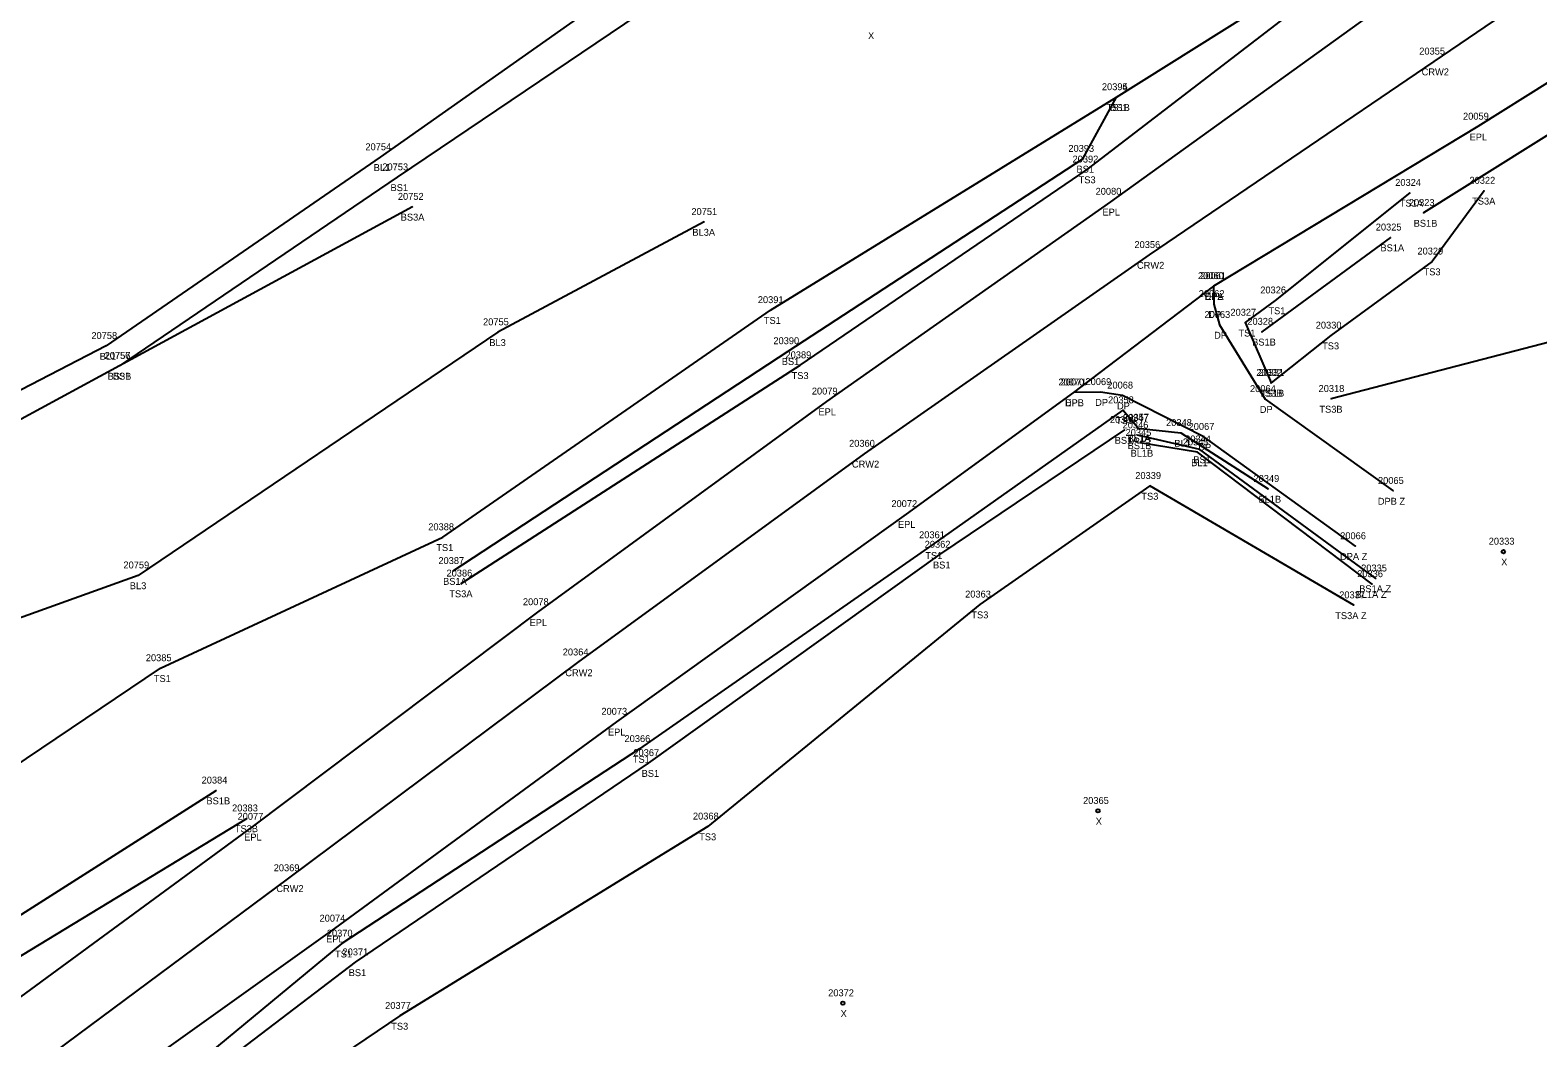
# Model space of a CAD drawing. Extents: x 1813127 to 1814107, y 1178171 to 1179078.
# Drawn here: x 1813586.1 to 1813803.8, y 1178473.8 to 1178619.3 of the extents above; entities that cross this region are included whole.
import ezdxf

# ---------------------------------------------------------------- set-up
doc = ezdxf.new("R2010")
doc.units = 0
for name, color, linetype in [('RD_DTM_BkLn1', 7, 'Continuous'), ('RD_DTM_BkLn2', 7, 'Continuous'), ('RD_EX_Driveway', 7, 'Continuous'), ('RD_EX_Driveway_txCode', 7, 'Continuous'), ('RD_EX_Road', 7, 'Continuous'), ('RD_EX_Road_txCode', 7, 'Continuous'), ('RD_SMD_Locator', 7, 'Continuous'), ('RD_SMD_Misc', 7, 'Continuous')]:
    doc.layers.add(name, color=color, linetype=linetype)

msp = doc.modelspace()

# ---------------------------------------------------------------- linework, layer by layer
at = {"layer": 'RD_DTM_BkLn1'}
for points in [[(1813684.91, 1178649.24), (1813672.9, 1178626.57), (1813636.59, 1178600.97), (1813597.02, 1178573.71), (1813553.38, 1178551.14), (1813526.62, 1178527.89)], [(1813831.28, 1178643.33), (1813821.11, 1178637.41), (1813809.78, 1178629.12), (1813788.78, 1178614.79), (1813747.67, 1178586.85), (1813706.5, 1178558.14), (1813665.11, 1178528), (1813623.37, 1178496.83), (1813582.75, 1178466.66)], [(1813683.38, 1178591.62), (1813653.58, 1178575.69), (1813601.65, 1178540.57), (1813550.07, 1178522.01), (1813545.91, 1178506.15)], [(1813745.95, 1178561.82), (1813752.22, 1178561.14), (1813764.83, 1178553.06)], [(1813779.84, 1178539.31), (1813754.64, 1178558.34), (1813746.36, 1178559.71)]]:
    msp.add_lwpolyline(points, dxfattribs=at)
at = {"layer": 'RD_DTM_BkLn2'}
for p, q in [((1813641.28, 1178593.81), (1813598.95, 1178570.83)), ((1813782.5, 1178589.38), (1813763.95, 1178575.76)), ((1813570.91, 1178482.75), (1813612.94, 1178509.5)), ((1813573.76, 1178478.94), (1813617.33, 1178505.47))]:
    msp.add_line(p, q, dxfattribs=at)
for points in [[(1813648.32, 1178539.4), (1813697.26, 1178570.92), (1813738.71, 1178599.2), (1813778.43, 1178629.72), (1813788.89, 1178635.21), (1813789.75, 1178645.61), (1813795.55, 1178639.4), (1813796.73, 1178649.77), (1813786.93, 1178659.75), (1813776.01, 1178666.91), (1813768.6, 1178671.47), (1813763.23, 1178675.13), (1813760.53, 1178679.87)], [(1813647.13, 1178541.2), (1813695.54, 1178572.96), (1813738.1, 1178600.74), (1813742.95, 1178609.65), (1813776.97, 1178631.04), (1813783.78, 1178636.69), (1813785.55, 1178637.95), (1813783.65, 1178657.07), (1813774.21, 1178663.42), (1813755.25, 1178670.65), (1813744.09, 1178675.31)], [(1813687.73, 1178647.6), (1813673.94, 1178621.63), (1813639.04, 1178598.07), (1813598.95, 1178570.83), (1813556.33, 1178547.73), (1813528.18, 1178524.13)], [(1814014.78, 1178443.42), (1813981.68, 1178475.25), (1813945.25, 1178510.83), (1813909.11, 1178545.75), (1813871.28, 1178580.16), (1813838.14, 1178611.58), (1813831.82, 1178617.25), (1813823.34, 1178615.53), (1813787.27, 1178592.92)], [(1813561.84, 1178498.2), (1813604.88, 1178527.17), (1813645.67, 1178546.08), (1813692.97, 1178578.89), (1813742.95, 1178609.65)], [(1813893.16, 1178338.84), (1813921.32, 1178364.43), (1813929.94, 1178352.15), (1813936.66, 1178353.94), (1813964.13, 1178381.53), (1813993.38, 1178417.59), (1814007.74, 1178441.51), (1813972.38, 1178457.8), (1813931.97, 1178507.78), (1813904.27, 1178536.29), (1813860.78, 1178571.07), (1813835.97, 1178602.37), (1813828.98, 1178599.83), (1813813.84, 1178586.1), (1813811.52, 1178575.86), (1813773.95, 1178566.06)], [(1813785.3, 1178595.83), (1813765.84, 1178580.29), (1813761.51, 1178577.07), (1813765.25, 1178568.38)], [(1813796.03, 1178596.13), (1813788.52, 1178585.91), (1813773.87, 1178575.21), (1813765.25, 1178568.38)], [(1813746.03, 1178561.9), (1813743.83, 1178564.42), (1813716.29, 1178544.93), (1813674.06, 1178515.49), (1813631.05, 1178487.38), (1813591.54, 1178454.7)], [(1813744.11, 1178561.57), (1813717.38, 1178543.56), (1813675.31, 1178513.46), (1813633, 1178484.68), (1813592.1, 1178453.49)], [(1813780.39, 1178540.13), (1813754.97, 1178558.77), (1813745.96, 1178560.8)], [(1813777.22, 1178536.25), (1813747.77, 1178553.49), (1813723.22, 1178536.36), (1813683.91, 1178504.3), (1813639.44, 1178476.94), (1813596.75, 1178448.06)]]:
    msp.add_lwpolyline(points, dxfattribs=at)
at = {"layer": 'RD_EX_Driveway'}
for points in [[(1813756.93, 1178582.36), (1813756.99, 1178579.76), (1813757.82, 1178576.75), (1813764.4, 1178566.04), (1813782.88, 1178552.77)], [(1813777.44, 1178544.79), (1813755.53, 1178560.58), (1813743.79, 1178566.55), (1813740.64, 1178567.05), (1813736.74, 1178567)]]:
    msp.add_lwpolyline(points, dxfattribs=at)
at = {"layer": 'RD_EX_Road'}
for points in [[(1813577.25, 1178474.27), (1813618.17, 1178504.26), (1813659.38, 1178535.26), (1813701.1, 1178565.69), (1813742.11, 1178594.54), (1813782.72, 1178623.8), (1813791.22, 1178630.12), (1813798.98, 1178638.62), (1813801.09, 1178645.46), (1813800.26, 1178651.57), (1813775.58, 1178673.13), (1813768.46, 1178675.91), (1813762.33, 1178681.89)], [(1813815.99, 1178618.51), (1813795.14, 1178605.39), (1813756.93, 1178582.36), (1813736.74, 1178567), (1813712.58, 1178549.43), (1813670.71, 1178519.43), (1813630, 1178489.55), (1813588.23, 1178459.7)]]:
    msp.add_lwpolyline(points, dxfattribs=at)
at = {"layer": 'RD_SMD_Locator'}
for centre, radius in [((1813788.78, 1178614.79), 0.001), ((1813742.95, 1178609.65), 0.001), ((1813742.95, 1178609.65), 0.001), ((1813795.14, 1178605.39), 0.001), ((1813636.59, 1178600.97), 0.001), ((1813738.1, 1178600.74), 0.001), ((1813639.04, 1178598.07), 0.001), ((1813738.71, 1178599.2), 0.001), ((1813785.3, 1178595.83), 0.001), ((1813796.03, 1178596.13), 0.001), ((1813641.28, 1178593.81), 0.001), ((1813742.11, 1178594.54), 0.001), ((1813683.38, 1178591.62), 0.001), ((1813787.27, 1178592.92), 0.001), ((1813782.5, 1178589.38), 0.001), ((1813747.67, 1178586.85), 0.001), ((1813788.52, 1178585.91), 0.001), ((1813756.93, 1178582.36), 0.001), ((1813756.93, 1178582.36), 0.001), ((1813765.84, 1178580.29), 0.001), ((1813692.97, 1178578.89), 0.001), ((1813756.99, 1178579.76), 0.001), ((1813653.58, 1178575.69), 0.001), ((1813757.82, 1178576.75), 0.001), ((1813761.51, 1178577.07), 0.001), ((1813763.95, 1178575.76), 0.001), ((1813597.02, 1178573.71), 0.001), ((1813773.87, 1178575.21), 0.001), ((1813695.54, 1178572.96), 0.001), ((1813598.95, 1178570.83), 0.001), ((1813598.95, 1178570.83), 0.001), ((1813697.26, 1178570.92), 0.001), ((1813736.74, 1178567), 0.001), ((1813736.74, 1178567), 0.001), ((1813740.64, 1178567.05), 0.001), ((1813765.25, 1178568.38), 0.001), ((1813765.25, 1178568.38), 0.001), ((1813701.1, 1178565.69), 0.001), ((1813743.79, 1178566.55), 0.001), ((1813764.4, 1178566.04), 0.001), ((1813773.95, 1178566.06), 0.001), ((1813743.83, 1178564.42), 0.001), ((1813744.11, 1178561.57), 0.001), ((1813745.95, 1178561.82), 0.001), ((1813745.96, 1178560.8), 0.001), ((1813746.03, 1178561.9), 0.001), ((1813752.22, 1178561.14), 0.001), ((1813755.53, 1178560.58), 0.001), ((1813706.5, 1178558.14), 0.001), ((1813746.36, 1178559.71), 0.001), ((1813754.64, 1178558.34), 0.001), ((1813754.97, 1178558.77), 0.001), ((1813747.77, 1178553.49), 0.001), ((1813764.83, 1178553.06), 0.001), ((1813782.88, 1178552.77), 0.001), ((1813712.58, 1178549.43), 0.001), ((1813645.67, 1178546.08), 0.001), ((1813716.29, 1178544.93), 0.001), ((1813717.38, 1178543.56), 0.001), ((1813777.44, 1178544.79), 0.001), ((1813798.81, 1178544), 0.25), ((1813647.13, 1178541.2), 0.001), ((1813601.65, 1178540.57), 0.001), ((1813648.32, 1178539.4), 0.001), ((1813779.84, 1178539.31), 0.001), ((1813780.39, 1178540.13), 0.001), ((1813723.22, 1178536.36), 0.001), ((1813659.38, 1178535.26), 0.001), ((1813777.22, 1178536.25), 0.001), ((1813665.11, 1178528), 0.001), ((1813604.88, 1178527.17), 0.001), ((1813670.71, 1178519.43), 0.001), ((1813674.06, 1178515.49), 0.001), ((1813675.31, 1178513.46), 0.001), ((1813612.94, 1178509.5), 0.001), ((1813740.26, 1178506.55), 0.25), ((1813617.33, 1178505.47), 0.001), ((1813618.17, 1178504.26), 0.001), ((1813683.91, 1178504.3), 0.001), ((1813623.37, 1178496.83), 0.001), ((1813630, 1178489.55), 0.001), ((1813631.05, 1178487.38), 0.001), ((1813633, 1178484.68), 0.001), ((1813703.41, 1178478.77), 0.25), ((1813639.44, 1178476.94), 0.001)]:
    msp.add_circle(centre, radius, dxfattribs=at)

# ---------------------------------------------------------------- texts
at = {"layer": 'RD_EX_Driveway_txCode'}
for s, p in [('20061', (1813755.03, 1178583.36)), ('20062', (1813754.81, 1178580.76)), ('DPA', (1813755.66, 1178580.36)), ('20063', (1813755.64, 1178577.75)), ('DP', (1813756.21, 1178577.76)), ('DP', (1813757.04, 1178574.75)), ('20070', (1813734.55, 1178568)), ('20069', (1813738.46, 1178568.05)), ('20068', (1813741.61, 1178567.55)), ('20064', (1813762.22, 1178567.04)), ('DPB', (1813735.49, 1178565)), ('DP', (1813739.86, 1178565.05)), ('DP', (1813743.01, 1178564.55)), ('DP', (1813763.63, 1178564.04)), ('20067', (1813753.35, 1178561.58)), ('DP', (1813754.75, 1178558.58)), ('20065', (1813780.7, 1178553.77)), ('DPB Z', (1813780.68, 1178550.77)), ('20066', (1813775.24, 1178545.79)), ('DPA Z', (1813775.22, 1178542.79))]:
    msp.add_text(s, height=1, dxfattribs=at).set_placement(p)
at = {"layer": 'RD_EX_Road_txCode'}
for s, p in [('20059', (1813792.98, 1178606.39)), ('EPL', (1813793.93, 1178603.39)), ('20080', (1813739.92, 1178595.54)), ('EPL', (1813740.91, 1178592.54)), ('20060', (1813754.71, 1178583.36)), ('EPL', (1813755.73, 1178580.36)), ('20071', (1813734.87, 1178568)), ('20079', (1813698.94, 1178566.69)), ('EPL', (1813699.9, 1178563.69)), ('EPL', (1813735.54, 1178565)), ('20072', (1813710.43, 1178550.43)), ('EPL', (1813711.38, 1178547.43)), ('20078', (1813657.22, 1178536.26)), ('EPL', (1813658.18, 1178533.26)), ('20073', (1813668.55, 1178520.43)), ('EPL', (1813669.5, 1178517.43)), ('20077', (1813616.01, 1178505.26)), ('EPL', (1813616.96, 1178502.26)), ('20074', (1813627.85, 1178490.55)), ('EPL', (1813628.8, 1178487.55))]:
    msp.add_text(s, height=1, dxfattribs=at).set_placement(p)
at = {"layer": 'RD_SMD_Misc'}
for s, p in [('X', (1813707.06, 1178618.02)), ('20355', (1813786.66, 1178615.79)), ('CRW2', (1813787.01, 1178612.79)), ('20394', (1813740.83, 1178610.65)), ('20395', (1813740.83, 1178610.65)), ('TS1B', (1813741.52, 1178607.65)), ('BS1', (1813742.01, 1178607.65)), ('20754', (1813634.47, 1178601.97)), ('20393', (1813735.99, 1178601.74)), ('BL1', (1813635.67, 1178598.97)), ('20753', (1813636.92, 1178599.07)), ('20392', (1813736.59, 1178600.2)), ('BS1', (1813737.16, 1178598.74)), ('TS3', (1813737.47, 1178597.2)), ('20324', (1813783.19, 1178596.83)), ('20322', (1813793.91, 1178597.13)), ('BS1', (1813638.1, 1178596.07)), ('20752', (1813639.16, 1178594.81)), ('TS3A', (1813794.3, 1178594.13)), ('20751', (1813681.55, 1178592.62)), ('TS1A', (1813783.85, 1178593.83)), ('20323', (1813785.15, 1178593.92)), ('BS3A', (1813639.57, 1178591.81)), ('20325', (1813780.38, 1178590.38)), ('BS1B', (1813785.85, 1178590.92)), ('BL3A', (1813681.69, 1178589.62)), ('20356', (1813745.53, 1178587.85)), ('BS1A', (1813781.06, 1178587.38)), ('20329', (1813786.4, 1178586.91)), ('CRW2', (1813745.9, 1178584.85)), ('TS3', (1813787.28, 1178583.91)), ('20326', (1813763.7, 1178581.29)), ('20391', (1813691.14, 1178579.89)), ('20755', (1813651.46, 1178576.69)), ('TS1', (1813692.01, 1178576.89)), ('20327', (1813759.39, 1178578.07)), ('20328', (1813761.83, 1178576.76)), ('TS1', (1813764.88, 1178578.29)), ('20758', (1813594.9, 1178574.71)), ('TS1', (1813760.55, 1178575.07)), ('20330', (1813771.71, 1178576.21)), ('BL3', (1813652.37, 1178573.69)), ('20390', (1813693.39, 1178573.96)), ('BS1B', (1813762.53, 1178573.76)), ('TS3', (1813772.63, 1178573.21)), ('BL1', (1813596.1, 1178571.71)), ('20756', (1813596.8, 1178571.83)), ('20757', (1813596.83, 1178571.83)), ('BS1', (1813694.6, 1178570.96)), ('20389', (1813695.14, 1178571.92)), ('BS3B', (1813597.25, 1178568.83)), ('BS1', (1813598, 1178568.83)), ('TS3', (1813696.02, 1178568.92)), ('20332', (1813763.13, 1178569.38)), ('20331', (1813763.41, 1178569.38)), ('TS3B', (1813763.53, 1178566.38)), ('TS1B', (1813763.82, 1178566.38)), ('20318', (1813772.12, 1178567.06)), ('20358', (1813741.72, 1178565.42)), ('TS3B', (1813772.24, 1178564.06)), ('20359', (1813741.99, 1178562.57)), ('TS1', (1813742.87, 1178562.42)), ('20346', (1813743.82, 1178561.8)), ('20347', (1813743.84, 1178562.82)), ('20357', (1813743.91, 1178562.9)), ('20348', (1813750.1, 1178562.14)), ('BS1A', (1813742.68, 1178559.57)), ('20345', (1813744.25, 1178560.71)), ('TS1A', (1813744.58, 1178559.9)), ('BL1A', (1813744.54, 1178559.82)), ('20343', (1813752.52, 1178559.34)), ('20344', (1813752.85, 1178559.77)), ('20360', (1813704.32, 1178559.14)), ('BS1B', (1813744.54, 1178558.8)), ('BL1B', (1813744.97, 1178557.71)), ('BL1', (1813751.3, 1178559.14)), ('CRW2', (1813704.73, 1178556.14)), ('BL1', (1813753.72, 1178556.34)), ('BS1', (1813754.03, 1178556.77)), ('20339', (1813745.65, 1178554.49)), ('20349', (1813762.72, 1178554.06)), ('TS3', (1813746.53, 1178551.49)), ('BL1B', (1813763.44, 1178551.06)), ('20388', (1813643.55, 1178547.08)), ('TS1', (1813644.71, 1178544.08)), ('20361', (1813714.43, 1178545.93)), ('20362', (1813715.24, 1178544.56)), ('20333', (1813796.69, 1178545)), ('20387', (1813645.01, 1178542.2)), ('TS1', (1813715.33, 1178542.93)), ('X', (1813798.49, 1178542)), ('20759', (1813599.53, 1178541.57)), ('20386', (1813646.18, 1178540.4)), ('BS1', (1813716.44, 1178541.56)), ('20336', (1813777.7, 1178540.31)), ('20335', (1813778.27, 1178541.13)), ('BL3', (1813600.45, 1178538.57)), ('BS1A', (1813645.69, 1178539.2)), ('BS1A Z', (1813777.99, 1178538.13)), ('TS3A', (1813646.59, 1178537.4)), ('20363', (1813721.08, 1178537.36)), ('20337', (1813775.1, 1178537.25)), ('BL1A Z', (1813777.47, 1178537.31)), ('TS3', (1813721.98, 1178534.36)), ('TS3A Z', (1813774.53, 1178534.25)), ('20364', (1813662.97, 1178529)), ('20385', (1813602.76, 1178528.17)), ('TS1', (1813603.92, 1178525.17)), ('CRW2', (1813663.34, 1178526)), ('20366', (1813671.89, 1178516.49)), ('20367', (1813673.17, 1178514.46)), ('TS1', (1813673.09, 1178513.49)), ('BS1', (1813674.36, 1178511.46)), ('20384', (1813610.82, 1178510.5)), ('BS1B', (1813611.52, 1178507.5)), ('20365', (1813738.11, 1178507.55)), ('20383', (1813615.22, 1178506.47)), ('20368', (1813681.77, 1178505.3)), ('TS3B', (1813615.62, 1178503.47)), ('X', (1813739.94, 1178504.55)), ('TS3', (1813682.67, 1178502.3)), ('20369', (1813621.23, 1178497.83)), ('CRW2', (1813621.61, 1178494.83)), ('20370', (1813628.9, 1178488.38)), ('TS1', (1813630.09, 1178485.38)), ('20371', (1813631.17, 1178485.68)), ('BS1', (1813632.06, 1178482.68)), ('20372', (1813701.3, 1178479.77)), ('20377', (1813637.32, 1178477.94)), ('X', (1813703.1, 1178476.77)), ('TS3', (1813638.2, 1178474.94))]:
    msp.add_text(s, height=1, dxfattribs=at).set_placement(p)

doc.saveas('drawing.dxf')
